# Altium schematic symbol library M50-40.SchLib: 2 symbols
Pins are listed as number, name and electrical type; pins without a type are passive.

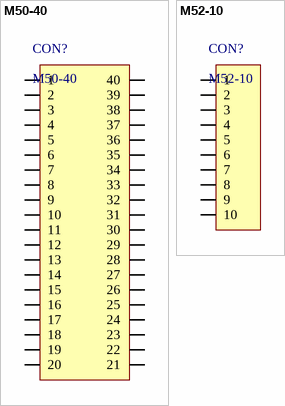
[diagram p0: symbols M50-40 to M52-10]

## M50-40
designator CON?
M50 Series Female Header Connector
footprint M50-40 (M50 Series Female Header Connector)
pins: 1, 2, 3, 4, 5, 6, 7, 8, 9, 10, 11, 12, 13, 14, 15, 16, 17, 18, 19, 20, 21, 22, 23, 24, 25, 26, 27, 28, 29, 30, 31, 32, 33, 34, 35, 36, 37, 38, 39, 40

## M52-10
designator CON?
M52 Series Female Header Connector
footprint M52-10 (M52 Series Connector 10 Pin)
pins: 1, 2, 3, 4, 5, 6, 7, 8, 9, 10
